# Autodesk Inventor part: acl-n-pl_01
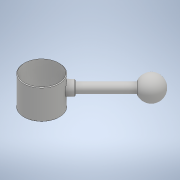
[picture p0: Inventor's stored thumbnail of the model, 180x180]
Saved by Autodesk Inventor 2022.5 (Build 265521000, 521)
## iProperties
Part Number: acl-n-pl_01
Material: 一般
Document SubType Name: Modeling
Designer: ImaoCorp
Density: 1 g/cm^3
Appearance: 既定
Author: ImaoCorp
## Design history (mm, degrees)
feature "acl-n-pl_01"
node "ソリッド1"
